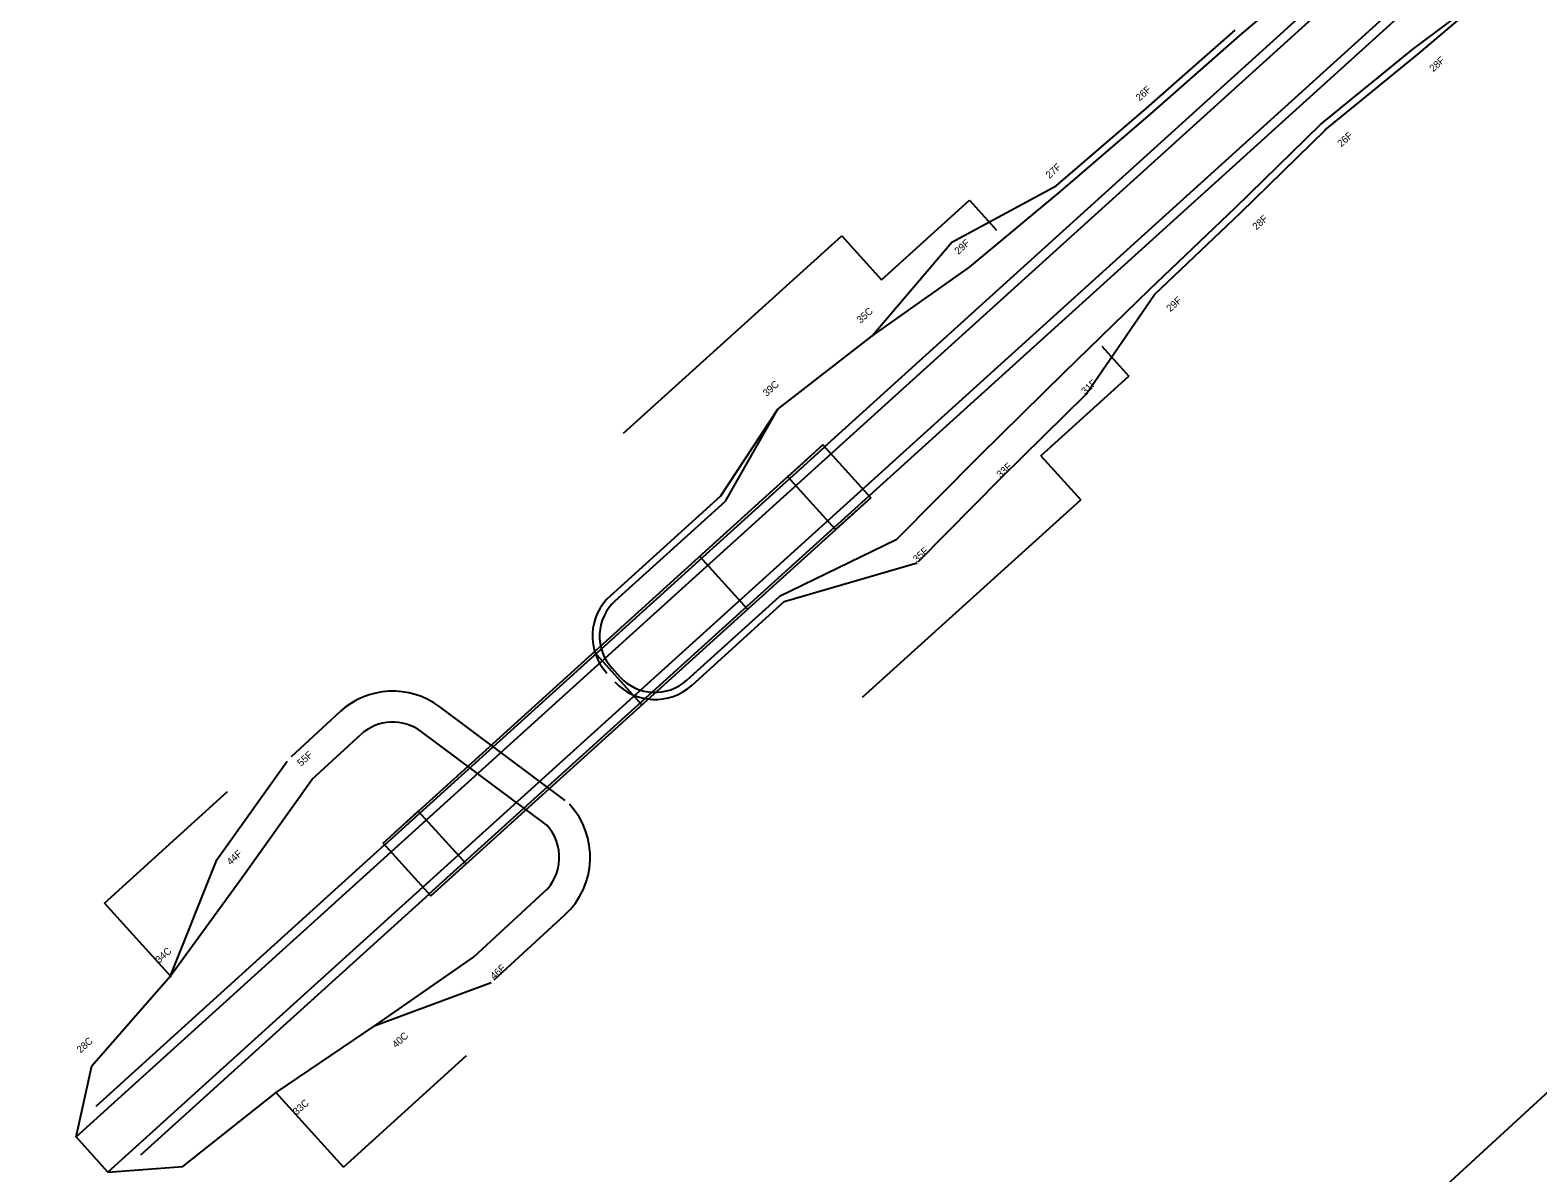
# Model space of a CAD drawing. Extents: x 2116464 to 2118397, y 979599 to 981222.
# Drawn here: x 2117138 to 2117773, y 979970 to 980452 of the extents above; entities that cross this region are included whole.
import ezdxf

# ---------------------------------------------------------------- set-up
doc = ezdxf.new("R2010")
doc.units = 0
for name, color, linetype in [('RD_PD_Bridge', 7, 'Continuous'), ('RD_PD_CstnLmt', 7, 'Continuous'), ('RD_PD_CstnLmt_TX', 7, 'Continuous'), ('RD_PD_DR_ErosCtrl', 7, 'Continuous'), ('RD_PD_Final_TrvlWay', 7, 'Continuous'), ('RD_PD_GR', 7, 'Continuous'), ('RD_PD_RW', 7, 'Continuous'), ('RD_Sketch2', 7, 'Continuous')]:
    doc.layers.add(name, color=color, linetype=linetype)

msp = doc.modelspace()

# ---------------------------------------------------------------- linework, layer by layer
at = {"layer": 'RD_PD_Bridge'}
for p, q in [((2117286.24, 980109.02), (2117471.6, 980276.78)), ((2117286.97, 980108.22), (2117472.32, 980275.98)), ((2117305.65, 980087.58), (2117491, 980255.34)), ((2117306.38, 980086.78), (2117491.73, 980254.54)), ((2117439.83, 980207.57), (2117419.7, 980229.81)), ((2117395.34, 980167.3), (2117375.21, 980189.54))]:
    msp.add_line(p, q, dxfattribs=at)
for points in [[(2117456.77, 980263.36), (2117471.6, 980276.78), (2117491.73, 980254.54), (2117476.9, 980241.12)], [(2117286.24, 980109.02), (2117301.07, 980122.44), (2117321.2, 980100.2), (2117306.38, 980086.78)]]:
    msp.add_lwpolyline(points, close=True, dxfattribs=at)
at = {"layer": 'RD_PD_CstnLmt'}
for p, q in [((2117647.26, 980449.29), (2117685.2, 980481.88)), ((2117720.02, 980443.41), (2117760.21, 980473.62)), ((2117609.7, 980416.28), (2117647.26, 980449.29)), ((2117681.23, 980411.76), (2117720.02, 980443.41)), ((2117571.79, 980383.65), (2117609.7, 980416.28)), ((2117645.46, 980376.77), (2117681.23, 980411.76)), ((2117533.32, 980351.64), (2117571.79, 980383.65)), ((2117609.21, 980342.31), (2117645.46, 980376.77)), ((2117492.16, 980322.62), (2117533.32, 980351.64)), ((2117573.33, 980307.44), (2117609.21, 980342.31)), ((2117452.59, 980291.82), (2117492.16, 980322.62)), ((2117537.66, 980272.34), (2117573.33, 980307.44)), ((2117430.54, 980253.1), (2117452.59, 980291.82)), ((2117502.46, 980236.73), (2117537.66, 980272.34)), ((2117384.04, 980211.02), (2117430.54, 980253.1)), ((2117502.46, 980236.73), (2117453.25, 980212.97)), ((2117414.27, 980177.69), (2117453.25, 980212.97)), ((2117386.12, 980178.98), (2117382.74, 980182.66)), ((2117256.44, 980135.99), (2117276.85, 980154.75)), ((2117355.24, 980116.58), (2117302.34, 980156.05)), ((2117226.71, 980094.32), (2117256.44, 980135.99)), ((2117196.65, 980053.03), (2117226.71, 980094.32)), ((2117324.32, 980060.99), (2117354.05, 980088.32)), ((2117282.99, 980032.14), (2117324.32, 980060.99)), ((2117163.5, 980015.14), (2117196.65, 980053.03)), ((2117241.16, 980003.85), (2117282.99, 980032.14)), ((2117156.89, 979985.19), (2117163.5, 980015.14)), ((2117201.92, 979972.69), (2117241.16, 980003.85)), ((2117170.31, 979970.36), (2117201.92, 979972.69))]:
    msp.add_line(p, q, dxfattribs=at)
for centre, start, end in [((2117397.46, 980196.2), 132.14821, 222.58596), ((2117400.85, 980192.52), 222.58596, 312.14821), ((2117290.38, 980140.02), 53.2669, 132.58596), ((2117340.52, 980103.04), 312.58596, 42.58596)]:
    msp.add_arc(centre, 20, start, end, dxfattribs=at)
at = {"layer": 'RD_PD_DR_ErosCtrl'}
for p, q in [((2117721.82, 980441.02), (2117760.21, 980473.62)), ((2117607.72, 980418.53), (2117645.28, 980451.54)), ((2117683.12, 980409.44), (2117721.91, 980441.09)), ((2117569.84, 980385.92), (2117607.74, 980418.55)), ((2117647.56, 980374.62), (2117683.32, 980409.62)), ((2117525.83, 980362.27), (2117569.87, 980385.95)), ((2117611.28, 980340.13), (2117647.53, 980374.59)), ((2117492.16, 980322.62), (2117525.83, 980362.27)), ((2117582.45, 980298.17), (2117611.3, 980340.16)), ((2117546.77, 980263.08), (2117582.45, 980298.17)), ((2117428.52, 980255.33), (2117452.59, 980291.82)), ((2117511.7, 980227.59), (2117546.9, 980263.21)), ((2117382.03, 980213.25), (2117428.52, 980255.33)), ((2117455.26, 980210.74), (2117511.25, 980227.15)), ((2117416.28, 980175.46), (2117455.26, 980210.74)), ((2117247.64, 980145.56), (2117268.05, 980164.32)), ((2117363.02, 980126.99), (2117310.12, 980166.47)), ((2117216.13, 980101.87), (2117245.85, 980143.54)), ((2117196.65, 980053.03), (2117216.2, 980101.98)), ((2117333.12, 980051.42), (2117362.85, 980078.74)), ((2117282.99, 980032.14), (2117331.76, 980050.33))]:
    msp.add_line(p, q, dxfattribs=at)
for centre, radius, start, end in [((2117397.46, 980196.2), 23, 132.14821, 222.58596), ((2117400.85, 980192.52), 23, 222.58596, 312.14821), ((2117290.38, 980140.02), 33, 53.2669, 132.58596), ((2117340.52, 980103.04), 33, 312.58596, 42.58596)]:
    msp.add_arc(centre, radius, start, end, dxfattribs=at)
at = {"layer": 'RD_PD_Final_TrvlWay'}
for p, q in [((2117156.89, 979985.19), (2117730.06, 980503.98)), ((2117170.31, 979970.36), (2117743.49, 980489.15)), ((2117170.31, 979970.36), (2117156.89, 979985.19))]:
    msp.add_line(p, q, dxfattribs=at)
at = {"layer": 'RD_PD_GR'}
for p, q in [((2117472.27, 980276.04), (2117727.38, 980506.94)), ((2117746.17, 980486.18), (2117491.06, 980255.28)), ((2117165.32, 979998.22), (2117286.91, 980108.28)), ((2117305.7, 980087.52), (2117184.11, 979977.47))]:
    msp.add_line(p, q, dxfattribs=at)
at = {"layer": 'RD_PD_RW'}
for p, q in [((2117496.3, 980346.35), (2117533.37, 980379.9)), ((2117533.37, 980379.9), (2117544.78, 980367.3)), ((2117387.59, 980281.67), (2117479.53, 980364.88)), ((2117479.53, 980364.88), (2117496.3, 980346.35)), ((2117589.07, 980318.36), (2117600.48, 980305.76)), ((2117563.41, 980272.21), (2117600.48, 980305.76)), ((2117563.41, 980272.21), (2117580.18, 980253.67)), ((2117488.25, 980170.46), (2117580.18, 980253.67)), ((2117168.87, 980083.71), (2117220.77, 980130.69)), ((2117197.06, 980052.57), (2117168.87, 980083.71)), ((2117269.53, 979972.5), (2117321.43, 980019.47)), ((2117269.53, 979972.5), (2117241.35, 980003.64))]:
    msp.add_line(p, q, dxfattribs=at)
at = {"layer": 'RD_Sketch2'}
msp.add_lwpolyline([(2116741.06, 980247.26), (2117801.28, 981221.7), (2118396.78, 980573.79), (2117336.56, 979599.35)], close=True, dxfattribs=at)

# ---------------------------------------------------------------- texts
at = {"layer": 'RD_PD_CstnLmt_TX'}
for s, p in [('28F', (2117728.74, 980433.78)), ('26F', (2117605, 980421.47)), ('26F', (2117689.95, 980402.12)), ('27F', (2117567.1, 980388.84)), ('28F', (2117654.18, 980367.13)), ('29F', (2117528.63, 980356.83)), ('29F', (2117617.93, 980332.67)), ('35C', (2117487.46, 980327.81)), ('39C', (2117447.89, 980297.01)), ('31F', (2117582.05, 980297.8)), ('33F', (2117546.38, 980262.71)), ('35F', (2117511.18, 980227.09)), ('55F', (2117251.74, 980141.18)), ('44F', (2117222.01, 980099.51)), ('34C', (2117191.95, 980058.22)), ('46F', (2117333.04, 980051.35)), ('40C', (2117291.72, 980022.5)), ('28C', (2117158.81, 980020.33)), ('33C', (2117249.88, 979994.21))]:
    msp.add_text(s, height=3, rotation=42.14821, dxfattribs=at).set_placement(p)

doc.saveas('drawing.dxf')
